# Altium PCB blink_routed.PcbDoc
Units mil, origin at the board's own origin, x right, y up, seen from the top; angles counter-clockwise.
Board outline 1968.5 x 1181.1 mil, 2 copper layers (Top Layer, Bottom Layer); 3 components, 4 nets, 36 pads, 7 vias.
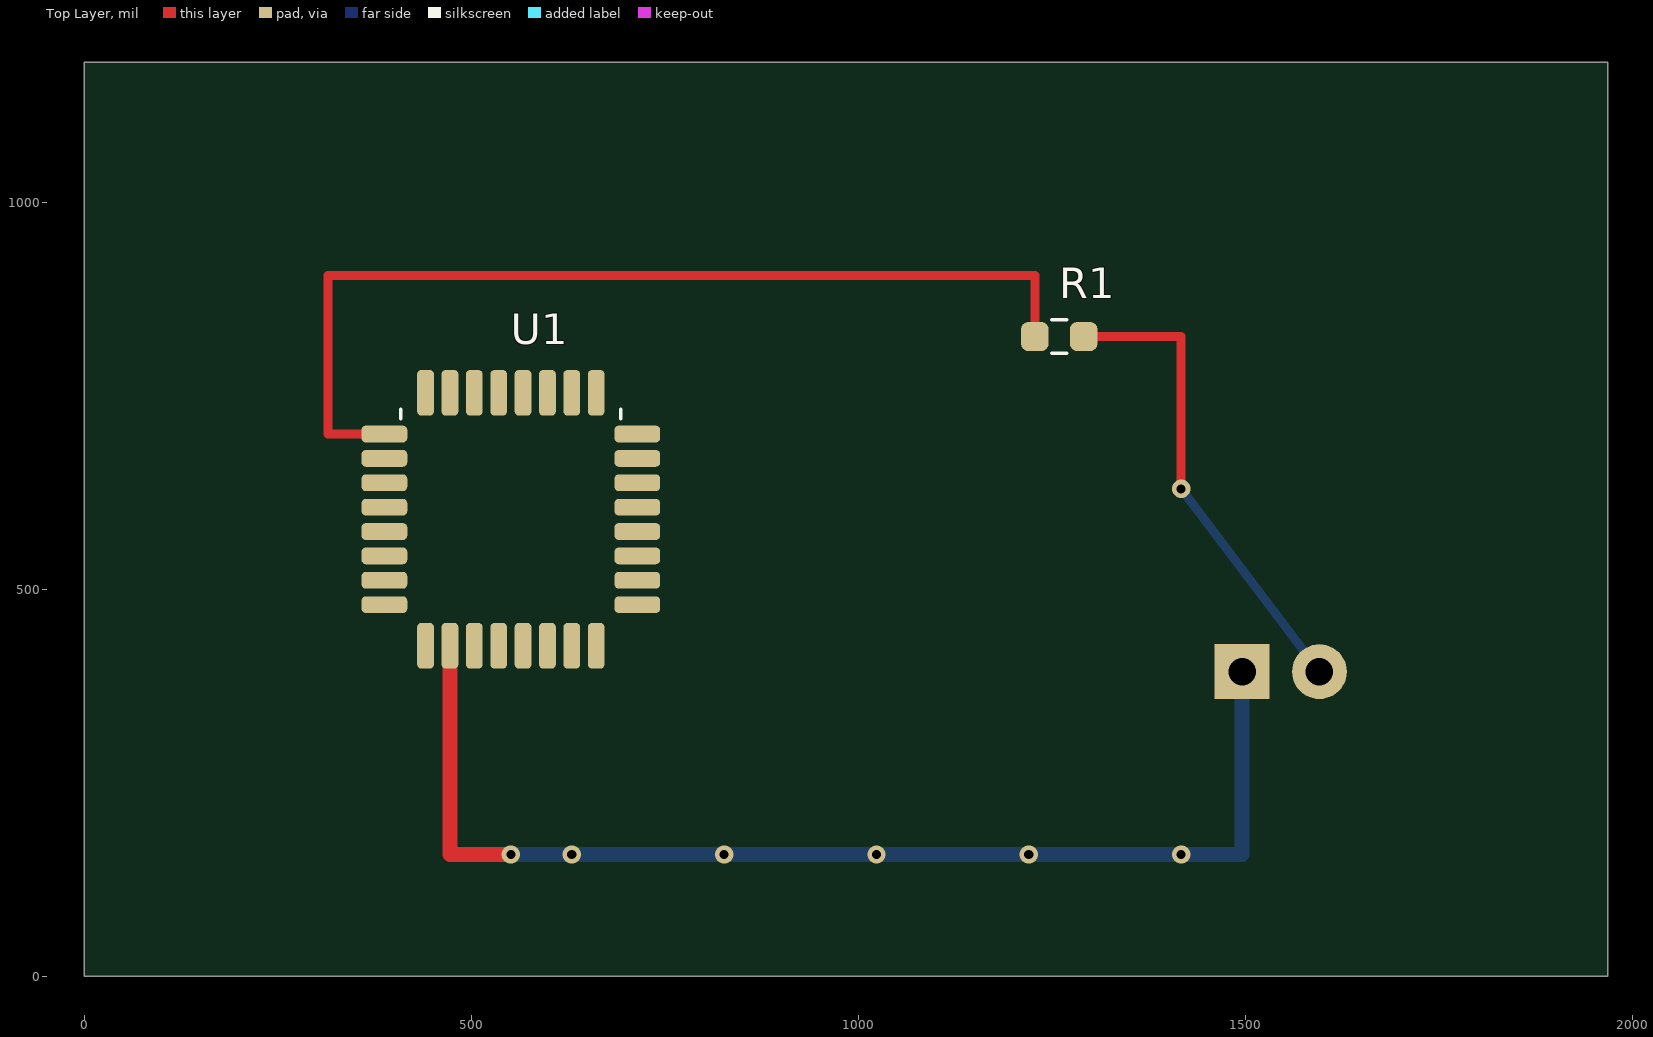
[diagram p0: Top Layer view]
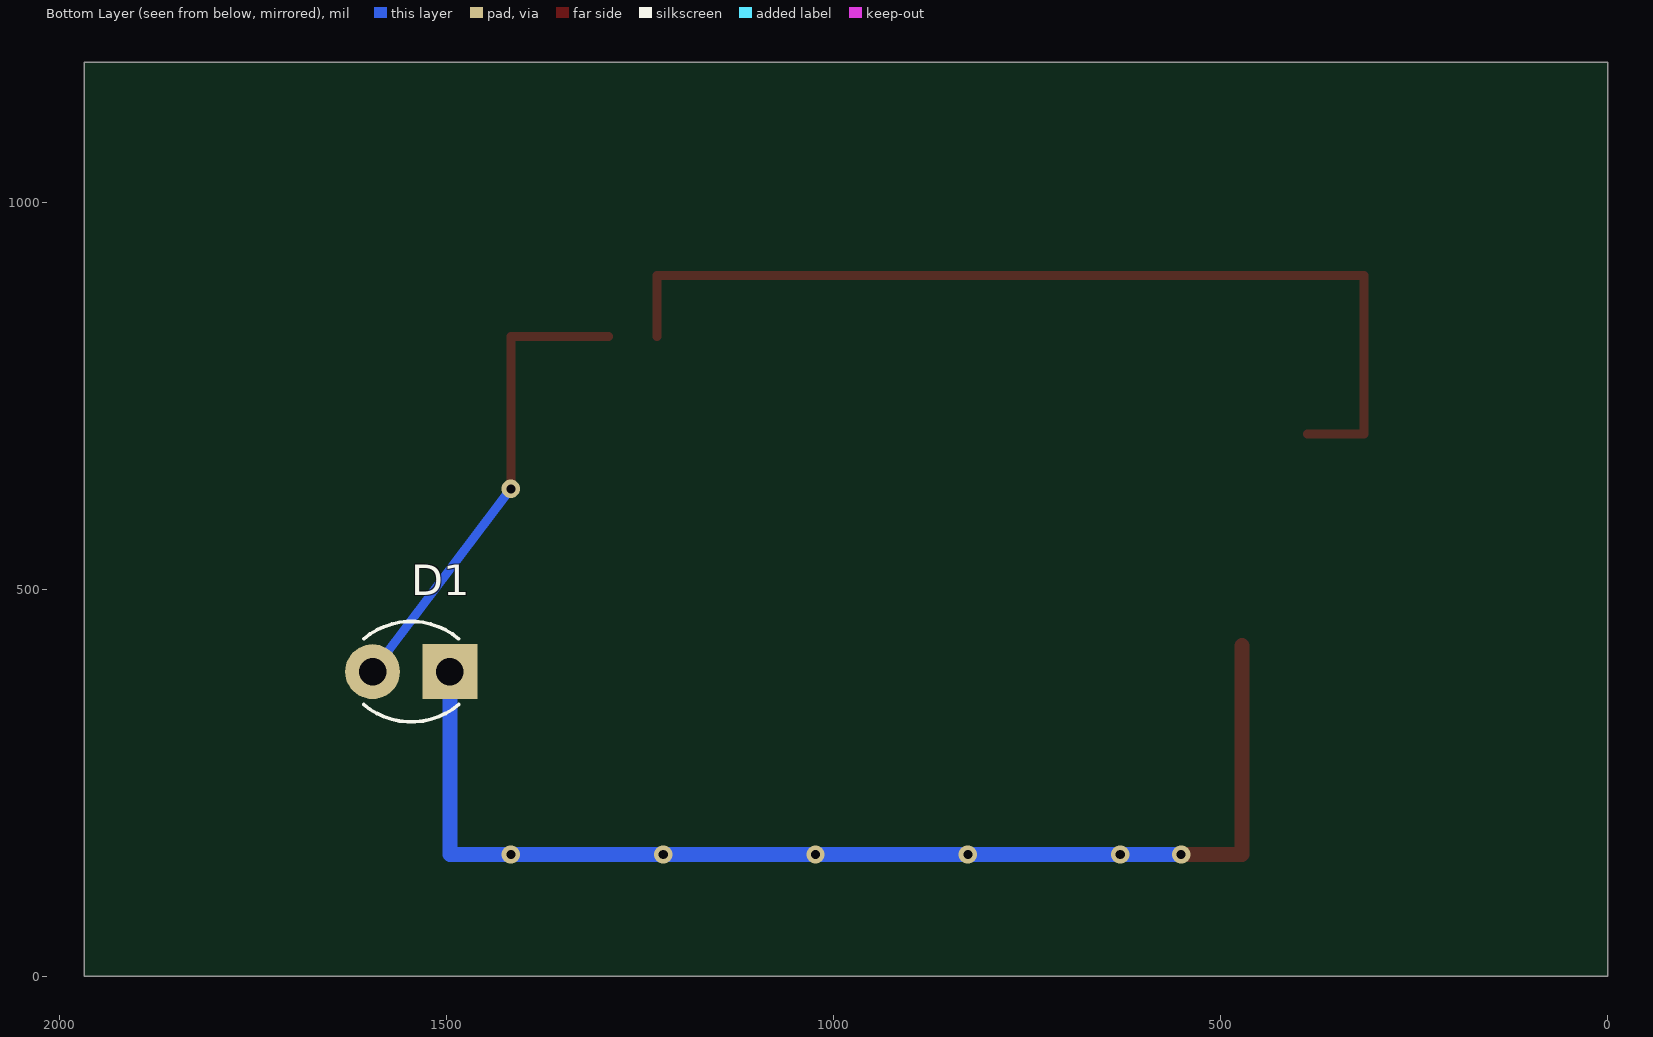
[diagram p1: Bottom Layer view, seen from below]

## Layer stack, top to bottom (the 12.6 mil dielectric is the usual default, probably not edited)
Top Solder: solder mask 0.4, Solder Resist, Dk 3.5
Top Layer: signal copper 1.4
Dielectric 1: dielectric 12.6, FR-4, Dk 4.8
Bottom Layer: signal copper 1.4
Bottom Solder: solder mask 0.4, Solder Resist, Dk 3.5

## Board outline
0,1181.1 1968.5,1181.1 1968.5,0 0,0

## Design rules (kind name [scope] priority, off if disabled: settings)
Clearance Clearance_PWR [InNetClass('PWR')] p1: gap=7.87 ignorepadtopadclearanceinfootprint=FALSE
Clearance [All] p2: gap=7.87 ignorepadtopadclearanceinfootprint=FALSE
RoutingVias [All] p1: holewidth=11.81 width=23.62 viastyle="Through Hole" minholewidth=11.81 minwidth=23.62 maxholewidth=11.81 maxwidth=23.62
Width Width_PWR [InNetClass('PWR')] p1: maxlimit=19.68 minlimit=19.68 preferedwidth=19.68
Width [All] p2: maxlimit=19.68 minlimit=9.84 preferedwidth=9.84

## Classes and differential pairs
net class PWR: GND VIN

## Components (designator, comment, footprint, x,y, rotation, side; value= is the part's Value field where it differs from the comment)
D1 "LED" Mini_LED_THT_3mm 1496.06,393.7 r0 bottom
R1 "330" Mini_R_0603 1259.84,826.77 r0 top
U1 "MCU" Mini_QFP-32_7x7mm_P0.8mm 551.18,590.55 r0 top locked

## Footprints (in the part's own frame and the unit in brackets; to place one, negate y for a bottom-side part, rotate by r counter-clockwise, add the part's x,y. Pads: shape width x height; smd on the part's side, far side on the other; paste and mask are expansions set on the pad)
Mini_LED_THT_3mm [mm]
  rect 1.8x1.8 hole 0.9: 1(0,0)
  round 1.8 hole 0.9: 2(2.54,0)
  silkscreen extent -0.29,-1.65 2.83,1.65
Mini_QFP-32_7x7mm_P0.8mm [mm]
  rrect50% 1.5x0.55 smd: 1(-4.15,2.8) 2(-4.15,2) 3(-4.15,1.2) 4(-4.15,0.4) 5(-4.15,-0.4) 6(-4.15,-1.2) 7(-4.15,-2) 8(-4.15,-2.8) 17(4.15,-2.8) 18(4.15,-2) 19(4.15,-1.2) 20(4.15,-0.4) 21(4.15,0.4) 22(4.15,1.2) 23(4.15,2) 24(4.15,2.8)
  rrect50% 0.55x1.5 smd: 9(-2.8,-4.15) 10(-2,-4.15) 11(-1.2,-4.15) 12(-0.4,-4.15) 13(0.4,-4.15) 14(1.2,-4.15) 15(2,-4.15) 16(2.8,-4.15) 25(2.8,4.15) 26(2,4.15) 27(1.2,4.15) 28(0.4,4.15) 29(-0.4,4.15) 30(-1.2,4.15) 31(-2,4.15) 32(-2.8,4.15)
  silkscreen extent -3.61,3.3 3.61,3.61
Mini_R_0603 [mm]
  rrect50% 0.9x0.95 smd: 1(-0.8,0) 2(0.8,0)
  silkscreen extent -0.25,-0.55 0.25,0.55

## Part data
D1: library part Mini_LED
R1: library part Mini_R
U1: library part Mini_QFP32_IC

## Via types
v1: diameter 23.62, hole 11.81, Top Layer to Bottom Layer, 7 vias

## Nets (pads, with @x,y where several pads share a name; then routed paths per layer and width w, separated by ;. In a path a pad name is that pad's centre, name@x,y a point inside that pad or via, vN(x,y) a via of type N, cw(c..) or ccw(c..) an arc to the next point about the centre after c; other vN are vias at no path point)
GND: D1.1 U1.10 | length 1529.5
  Top Layer w19.68: U1.10 472.44,157.48 v1(551.18,157.48)
  Bottom Layer w19.68: v1(551.18,157.48) 1496.06,157.48 D1.1
  other v1: 629.92,157.48 826.77,157.48 1023.62,157.48 1220.47,157.48 1417.32,157.48
LED_A: D1.2 R1.2 | length 619.1
  Top Layer w11.81: R1.2 1417.32,826.77 v1(1417.32,629.92)
  Bottom Layer w11.81: v1(1417.32,629.92) D1.2
LED_DRV: R1.1 U1.1 | length 1269.7
  Top Layer w11.81: U1.1 314.96,700.79 314.96,905.51 1228.35,905.51 R1.1
VIN: U1.9
pads on no net: U1.2 U1.3 U1.4 U1.5 U1.6 U1.7 U1.8 U1.11 U1.12 U1.13 U1.14 U1.15 U1.16 U1.17 U1.18 U1.19 U1.20 U1.21 U1.22 U1.23 U1.24 U1.25 U1.26 U1.27 U1.28 U1.29 U1.30 U1.31 U1.32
